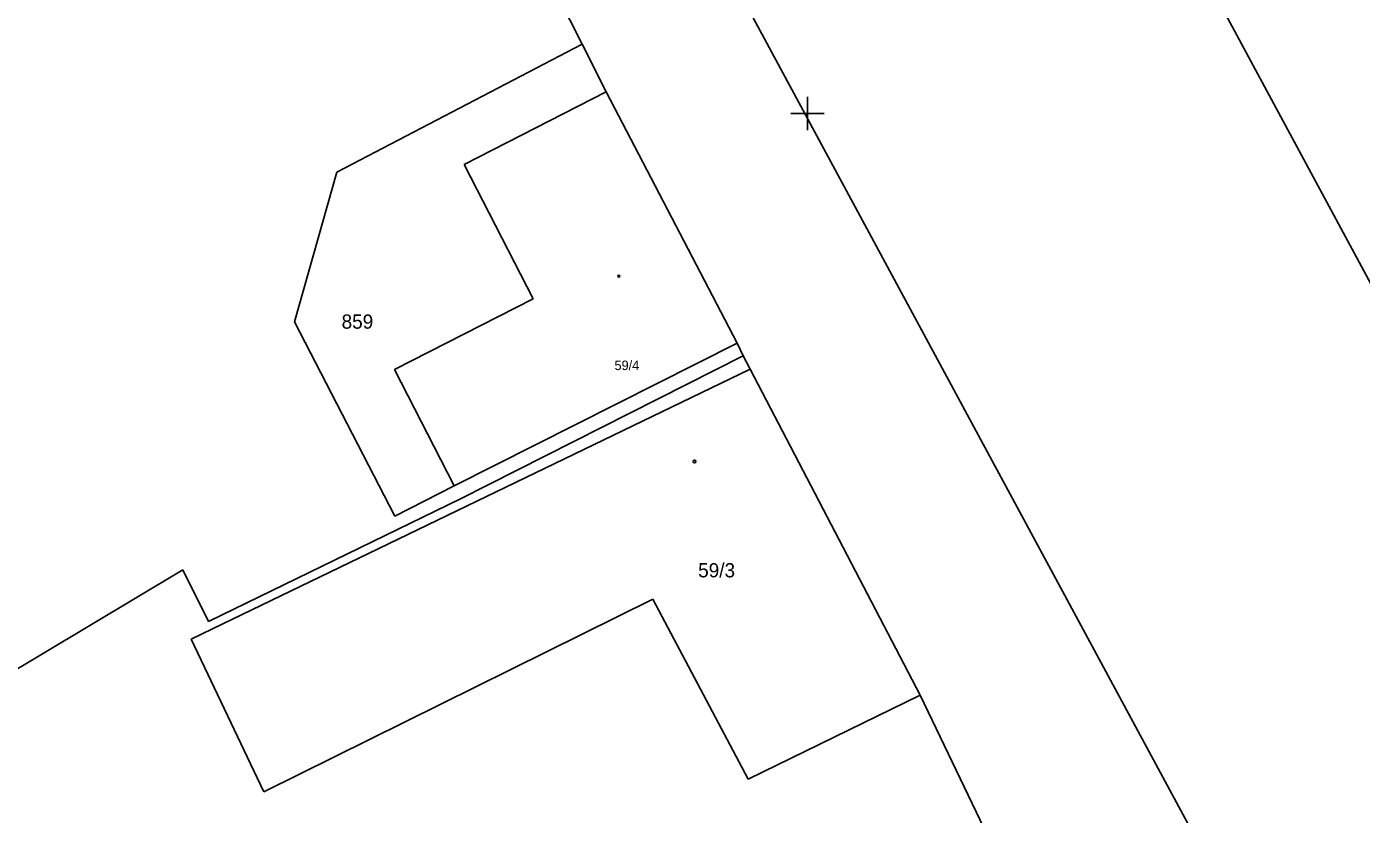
# Model space of a CAD drawing. Extents: x -703403 to -701924, y -1022520 to -1021856.
# Drawn here: x -702873.38 to -702833.42, y -1021996 to -1021972.4 of the extents above; entities that cross this region are included whole.
import ezdxf

# ---------------------------------------------------------------- set-up
doc = ezdxf.new("R2010")
doc.units = 0
for name, color, linetype in [('Z_hektometricka_sit', 7, 'Continuous'), ('Z_katastr_cisla_pozemkova', 7, 'Continuous'), ('Z_katastr_cisla_stavebni', 7, 'Continuous'), ('Z_katastr_hranice', 7, 'Continuous'), ('Z_katastr_vnitrni_kresba', 7, 'Continuous'), ('Z_katastr_znacky_budov', 7, 'Continuous')]:
    doc.layers.add(name, color=color, linetype=linetype)

msp = doc.modelspace()

# ---------------------------------------------------------------- linework, layer by layer
at = {"layer": 'Z_hektometricka_sit'}
for p, q in [((-702850, -1021974.5), (-702850, -1021975.5)), ((-702850.5, -1021975), (-702849.5, -1021975))]:
    msp.add_line(p, q, dxfattribs=at)
at = {"layer": 'Z_katastr_hranice'}
for p, q in [((-702847.21, -1021953.92), (-702823.381, -1021998.246)), ((-702834.365, -1022004.133), (-702857.83, -1021960.64)), ((-702856.75, -1021972.93), (-702859.63, -1021967.18)), ((-702864.09, -1021976.76), (-702856.75, -1021972.93)), ((-702856.75, -1021972.93), (-702856.03, -1021974.35)), ((-702856.03, -1021974.35), (-702860.28, -1021976.53)), ((-702852.1, -1021981.88), (-702856.03, -1021974.35)), ((-702860.28, -1021976.53), (-702858.21, -1021980.56)), ((-702865.36, -1021981.24), (-702864.09, -1021976.76)), ((-702858.21, -1021980.56), (-702862.37, -1021982.67)), ((-702862.36, -1021987.07), (-702865.36, -1021981.24)), ((-702852.1, -1021981.88), (-702860.58, -1021986.16)), ((-702851.92, -1021982.26), (-702852.1, -1021981.88)), ((-702860.39, -1021986.55), (-702851.92, -1021982.26)), ((-702851.72, -1021982.66), (-702851.92, -1021982.26)), ((-702862.37, -1021982.67), (-702860.58, -1021986.16)), ((-702846.62, -1021992.43), (-702851.72, -1021982.66)), ((-702860.58, -1021986.16), (-702862.36, -1021987.07)), ((-702867.94, -1021990.22), (-702860.39, -1021986.55)), ((-702877.62, -1021994.01), (-702868.7, -1021988.67)), ((-702868.7, -1021988.67), (-702867.94, -1021990.22)), ((-702844.59, -1021996.67), (-702846.62, -1021992.43))]:
    msp.add_line(p, q, dxfattribs=at)
at = {"layer": 'Z_katastr_vnitrni_kresba'}
for p, q in [((-702867.82, -1021990.44), (-702851.72, -1021982.66)), ((-702854.63, -1021989.55), (-702866.28, -1021995.33)), ((-702851.78, -1021994.95), (-702854.63, -1021989.55)), ((-702868.45, -1021990.75), (-702867.82, -1021990.44)), ((-702866.28, -1021995.33), (-702868.45, -1021990.75)), ((-702846.62, -1021992.43), (-702851.78, -1021994.95))]:
    msp.add_line(p, q, dxfattribs=at)
at = {"layer": 'Z_katastr_znacky_budov'}
for centre, radius in [((-702855.651, -1021979.88), 0.0293), ((-702853.382, -1021985.43), 0.0437)]:
    msp.add_circle(centre, radius, dxfattribs=at)

# ---------------------------------------------------------------- texts
at = {"layer": 'Z_katastr_cisla_pozemkova'}
msp.add_text('859', height=0.425, dxfattribs=at).set_placement((-702863.95, -1021981.45))
at = {"layer": 'Z_katastr_cisla_stavebni'}
for s, height, p in [('59/4', 0.285, (-702855.778, -1021982.69)), ('59/3', 0.425, (-702853.273, -1021988.9))]:
    msp.add_text(s, height=height, dxfattribs=at).set_placement(p)

doc.saveas('drawing.dxf')
